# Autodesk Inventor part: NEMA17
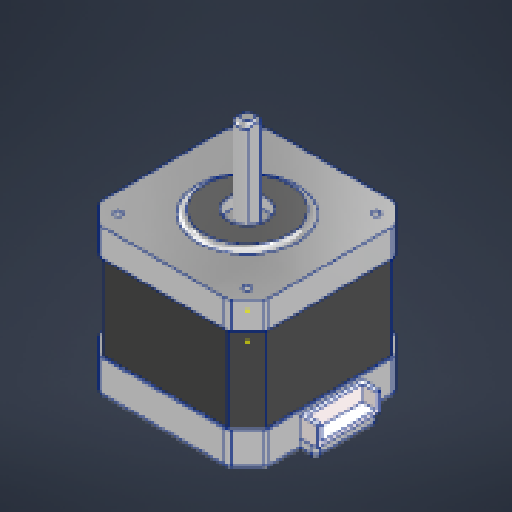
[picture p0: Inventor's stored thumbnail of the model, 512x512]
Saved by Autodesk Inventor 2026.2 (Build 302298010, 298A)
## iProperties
Created: 2025-09
Part Number: NEMA17
Material: 강철, 아연도금
Document SubType Name: Modeling
Designer: work
Density: 7.85 g/cm^3
Appearance: 알루미늄 - 평지
Author: work
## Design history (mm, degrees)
sketch "스케치1"
  geometry: L1 (0, 0)-(43, 0); L2 (43, 0)-(43, -43); L3 (43, -43)-(0, -43); L4 (0, -43)-(0, 0)
  constraints: 8 end point, 2 parallel, 1 horizontal, 1 perpendicular
  dimensions: "d0" = 43 distance of L2.end L3.end; "d1" = 43 distance of L1.end L2.end
extrude "돌출1" new body sketch "스케치1" distance "d2" = 9; taper "d3" = 0 deg
chamfer "모따기1" distance "d4" = 5; stored, may be unused: second distance "d5" = 2, angle "d6" = 45 deg
sketch "스케치2"
  geometry: L1 (-6.828, 0)-(-36.172, 0); L2 (-43, 6.828)-(-43, 36.172); L3 (-36.172, 43)-(-6.828, 43); L4 (0, 36.172)-(0, 6.828); L5 (-37.586, 0.586)-(-42.414, 5.414); L6 (-42.414, 37.586)-(-37.586, 42.414); L7 (-5.414, 42.414)-(-0.586, 37.586); L8 (-5.414, 0.586)-(-0.586, 5.414); A1 r 2 centre (-6.828, 2) between (-6.828, 0) and (-5.414, 0.586); A2 r 2 centre (-2, 6.828) between (-0.586, 5.414) and (0, 6.828); A3 r 2 centre (-2, 36.172) between (0, 36.172) and (-0.586, 37.586); A4 r 2 centre (-6.828, 41) between (-5.414, 42.414) and (-6.828, 43); A5 r 2 centre (-36.172, 41) between (-36.172, 43) and (-37.586, 42.414); A6 r 2 centre (-41, 36.172) between (-42.414, 37.586) and (-43, 36.172); A7 r 2 centre (-41, 6.828) between (-43, 6.828) and (-42.414, 5.414); A8 r 2 centre (-36.172, 2) between (-37.586, 0.586) and (-36.172, 0); 12 further points
  constraints: 24 point on line, 16 end point, 16 point on circle, 16 tangent, 8 centre point, 7 equal radius, 2 parallel, 1 horizontal, 1 perpendicular
  dimensions: "d7" = 43 distance of point (-43, 43) point (0, 43); "d8" = 43 distance of point (-43, 0) point (-43, 43); "d9" = 6 distance of point (-37, 0) point (-43, 0); "d10" = 6 distance of point (-43, 6) point (-43, 0) (= d9); "d11" = 6 distance of point (-43, 37) point (-43, 43) (= d9); "d12" = 6 distance of point (-37, 43) point (-43, 43) (= d11); "d13" = 6 distance of point (-6, 43) point (0, 43) (= d9); "d14" = 6 distance of point (0, 37) point (0, 43) (= d13); "d15" = 6 distance of point (-6, 0) point (0, 0) (= d9); "d16" = 6 distance of point (0, 6) point (0, 0) (= d15); "d17" = 2 radius of A1
extrude "돌출2" join sketch "스케치2" distance "d18" = 22; taper "d19" = 0 deg
sketch "스케치3"
  geometry: 1 further point
sketch "스케치4"
  geometry: L1 (0, 0)-(-43, 0); L2 (-43, 0)-(-43, 43); L3 (-43, 43)-(0, 43); L4 (0, 43)-(0, 0)
  constraints: 8 end point, 2 parallel, 1 horizontal, 1 perpendicular
  dimensions: "d20" = 43 distance of L2.end L3.end; "d21" = 43 distance of L1.end L2.end
extrude "돌출3" join sketch "스케치4" distance "d22" = 7; taper "d23" = 0 deg
chamfer "모따기2" distance "d24" = 5; stored, may be unused: second distance "d25" = 2, angle "d26" = 45 deg
sketch "스케치5"
  geometry: L1 (-5, 43)-(-38, 43) reference; L2 (0, 5)-(0, 38) reference; L3 (-19.5, 23)-(-19.5, 20); A1 r 2.5 centre (-21.5, 21.5) between (-19.5, 23) and (-19.5, 20); 1 further point
  constraints: 2 end point, 2 point on circle, 1 centre point, 1 vertical
  dimensions: "d27" = 5 diameter of A1; "d28" = 21.5 distance from line of L1 A1.centre; "d29" = 21.5 distance from line of L2 A1.centre; "d30" = 4.5 dimension on A1 L3
extrude "돌출4" join sketch "스케치5" distance "d31" = 22.2; taper "d32" = 0 deg
sketch "스케치6"
  geometry: C1 r 3.5 at (-21.5, -21.5); A1 r 2.5 centre (-21.5, -21.5) between (-19.5, -20) and (-19.5, -23) reference; 1 further point
  constraints: 1 centre point, 1 coincident
  dimensions: "d33" = 7 diameter of C1
extrude "돌출5" cut sketch "스케치6" distance "d34" = 3.5; taper "d35" = 0 deg
sketch "스케치7"
  geometry: L1 (0, -5)-(0, -38) reference; L2 (0, -13.5)-(4, -13.5); L3 (4, -13.5)-(4, -29.5); L4 (4, -29.5)-(0, -29.5); L5 (0, -29.5)-(0, -13.5); 3 further points
  constraints: 8 end point, 2 midpoint, 2 parallel, 1 horizontal, 1 perpendicular, 1 point on line
  dimensions: "d36" = 4 distance of L3.end L4.end; "d37" = 16 distance of L2.end L3.end
extrude "돌출6" join sketch "스케치7" distance "d38" = 3; taper "d39" = 0 deg
sketch "스케치8"
  geometry: L1 (0, 13.5)-(0, 29.5) reference; L2 (0, 13.5)-(4.5, 13.5); L3 (4.5, 13.5)-(4.5, 29.5); L4 (4.5, 29.5)-(0, 29.5); L5 (0, 29.5)-(0, 13.5); 2 further points
  constraints: 8 end point, 2 parallel, 1 horizontal, 1 perpendicular
  dimensions: "d40" = 4.5 distance of L4.end L3.end
extrude "돌출7" new body sketch "스케치8" distance "d41" = 5; taper "d42" = 0 deg
feature "쉘1" dims "d43" = 1
sketch "스케치9"
  geometry: C1 r 11 at (-21.5, 21.5); A1 r 2.5 centre (-21.5, 21.5) between (-19.5, 23) and (-19.5, 20) reference; 1 further point
  constraints: 1 centre point, 1 coincident
  dimensions: "d44" = 22 diameter of C1
extrude "돌출8" join sketch "스케치9" distance "d45" = 1; taper "d46" = 0 deg
sketch "스케치10"
  geometry: L1 (2, -1.5)-(2, 1.5) reference; C1 r 5 at (0, 0); A1 r 2.5 centre (0, 0) between (2, 1.5) and (2, -1.5) reference; A2 r 2.5 centre (0, 0) between (2, 1.5) and (2, -1.5) reference; 3 further points
  constraints: 1 centre point, 1 coincident
  dimensions: "d47" = 10 diameter of C1
extrude "돌출9" cut sketch "스케치10" distance "d48" = 3; taper "d49" = 0 deg
sketch "스케치11"
  geometry: 1 further point
sketch "스케치12"
  geometry: C1 r 5 at (0, 0) reference; C2 r 2.5 at (0, 0); 1 further point
  constraints: 1 centre point, 1 coincident
extrude "돌출10" join sketch "스케치12" distance "d50" = 1; taper "d51" = 0 deg
sketch "스케치13"
  geometry: L1 (0, 5)-(0, 38) reference; L2 (-38, 0)-(-5, 0) reference; L3 (-43, 38)-(-38, 43) reference; L4 (-43, 38)-(-43, 5) reference; L5 (-38, 0)-(-43, 5) reference; L6 (-38, 0)-(-5, 0) reference; L7 (0, 5)-(-5, 0) reference; L8 (0, 5)-(0, 38) reference; L9 (-5, 43)-(0, 38) reference; L10 (-5, 43)-(-38, 43) reference; C1 r 1 at (-5, 5); C2 r 11 at (-21.5, 21.5) reference; C3 r 1 at (-5, 38); C4 r 1 at (-38, 38); C5 r 1 at (-38, 5); 1 further point
  constraints: 4 centre point, 9 other
  dimensions: "d52" = 2 diameter of C1; "d53" = 4 distance edge to line of C1 L1; "d54" = 4 distance edge to line of C1 L2; "d57" = 360 deg dimension on C2.centre C1.centre (derived)
extrude "돌출11" cut sketch "스케치13" distance "d59" = 5; taper "d60" = 0 deg
sketch "스케치14"
  geometry: L1 (-5, 43)-(-38, 43) reference; L2 (-21.5, 43)-(-21.5, 0); L3 (-43, 38)-(-43, 5) reference; L4 (-43, 21.5)-(0, 21.5); L5 (0, 13.5)-(0, 29.5) reference; L6 (-43, 43)-(0, 43); L7 (0, 43)-(0, 0); L8 (0, 0)-(-43, 0); L9 (-43, 0)-(-43, 43); L10 (-43, 43)-(0, 0); L11 (0, 43)-(-43, 0); L12 (-42.5, 42.5)-(-0.5, 42.5); L13 (-0.5, 42.5)-(-0.5, 0.5); L14 (-0.5, 0.5)-(-42.5, 0.5); L15 (-42.5, 0.5)-(-42.5, 42.5); L16 (-42.5, 42.5)-(-0.5, 0.5); L17 (-0.5, 42.5)-(-42.5, 0.5); C1 r 2.5 at (-21.5, 21.5) reference; C2 r 3.5 at (-21.5, 21.5) reference; 7 further points
  constraints: 28 end point, 7 midpoint, 4 parallel, 2 horizontal, 2 perpendicular, 1 vertical
  dimensions: "d61" = 43 distance of L7.end L8.end; "d62" = 43 distance of L6.end L7.end; "d63" = 42 distance of L13.end L14.end; "d64" = 42 distance of L12.end L13.end
extrude "돌출12" cut sketch "스케치14" stored distance "d65" = 5; taper "d66" = 0 deg
fillet "모깎기1" dims "d67" = 2
chamfer "모따기3" distance "d68" = 1; stored, may be unused: second distance "d69" = 2, angle "d70" = 45 deg
fillet "모깎기2" dims "d71" = 1
node "솔리드1"
node "솔리드2"
node "투영된 루프1"
node "투영된 루프2"
node "스케치 - 원형 패턴1" dims "d57" = 360 deg (derived)
